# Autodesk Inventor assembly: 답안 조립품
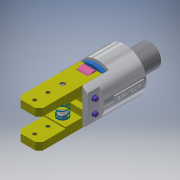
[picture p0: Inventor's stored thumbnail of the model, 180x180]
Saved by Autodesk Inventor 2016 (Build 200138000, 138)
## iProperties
Created: 2019-02
Part Number: 답안 조립품
Material: 일반
Document SubType Name: Assembly
Designer: 605-17
Author: 605-17
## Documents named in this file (11)
- C:\Users\605-17\Desktop\490207V7006\490207V1006\답안 조립품.iam
- C:\Users\605-17\Desktop\490207V7006\본체.ipt
- C:\Users\605-17\Desktop\490207V7006\O-링.ipt
- C:\Users\605-17\Desktop\490207V7006\피스톤.ipt
- C:\Users\605-17\Desktop\490207V7006\부시.ipt
- C:\Users\605-17\Desktop\490207V7006\평행핀 6x28.ipt
- C:\Users\605-17\Desktop\490207V7006\핑거.ipt
- C:\Users\605-17\Desktop\490207V7006\핀.ipt
- C:\Users\605-17\Desktop\490207V7006\E-링.ipt
- C:\Users\605-17\Desktop\490207V7006\가이드핀.ipt
- C:\Users\605-17\Desktop\490207V7006\스프링.ipt
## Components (13 placed, 6 different names)
1. O-링:1
2. 피스톤:1
3. O-링:2
4. 핑거:1
5. 핑거:2
6. 핀:1
7. 핀:2
8. E-링:1
9. E-링:2
10. E-링:3
11. E-링:4
12. 가이드핀:1
13. 가이드핀:2
